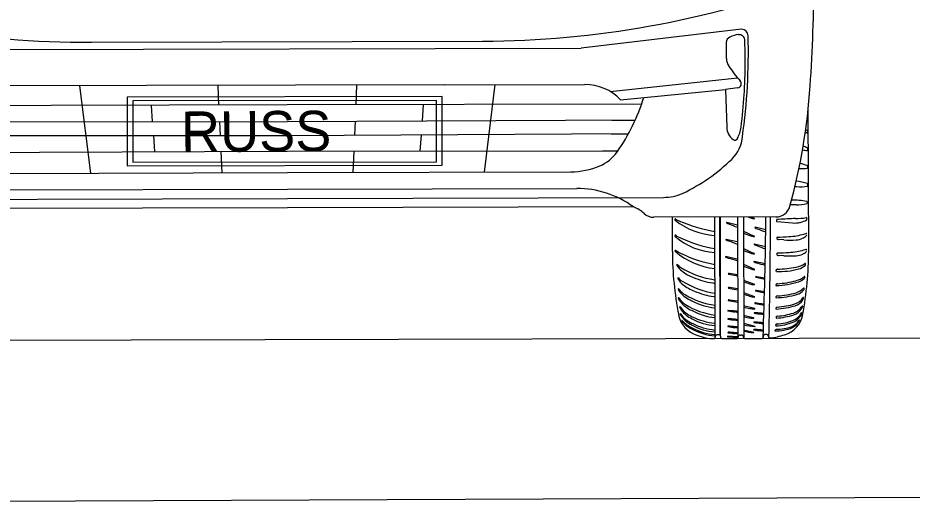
# Model space of a CAD drawing. Extents: x 10133 to 81668, y 4692 to 11018.
# Drawn here: x 28940.3 to 29064.3, y 5964.8 to 6032.5 of the extents above; entities that cross this region are included whole.
import ezdxf

# ---------------------------------------------------------------- set-up
doc = ezdxf.new("R2010")
doc.units = 0
for name, color, linetype in [('Cell', 7, 'Continuous'), ('Level 7', 7, 'Continuous'), ('PavementRemovalStage1', 7, 'Continuous'), ('SheetBorder', 7, 'Continuous')]:
    doc.layers.add(name, color=color, linetype=linetype)

msp = doc.modelspace()

# ---------------------------------------------------------------- linework, layer by layer
at = {"layer": 'Cell'}
for p, q in [((29040.67, 6030.95), (29018.43, 6028.34)), ((28950.5, 6029.14), (29004.76, 6029.28)), ((28936.84, 6028.13), (29018.43, 6028.34)), ((29022.47, 6022.31), (29040.1, 6024.21)), ((28999.45, 6023.24), (28936.34, 6023.08)), ((28948.84, 6023.11), (28950.37, 6010.99)), ((28968.02, 6023.16), (28968.15, 6020.42)), ((28987.27, 6023.21), (28987.16, 6020.47)), ((28999.45, 6023.24), (29018.95, 6023.29)), ((29006.45, 6023.26), (29004.99, 6011.14)), ((29040.13, 6022.84), (29038.46, 6022.58)), ((28958.77, 6020.39), (28958.95, 6018.13)), ((28996.53, 6020.49), (28996.37, 6018.23)), ((29049.98, 6000.18), (29049.93, 6020)), ((28968.26, 6018.14), (28968.35, 6016.2)), ((28987.06, 6018.19), (28986.98, 6016.25)), ((29022.7, 6018.33), (29025.92, 6018.34)), ((28996.23, 6016.3), (28996.07, 6014.05)), ((29022.61, 6016.42), (29024.97, 6016.43)), ((29049.74, 6016.58), (29049.74, 6016.58)), ((29049.8, 6016.83), (29049.79, 6016.64)), ((28959.1, 6016.21), (28959.27, 6013.96)), ((28968.45, 6013.99), (28968.59, 6011.04)), ((28986.89, 6014.03), (28986.76, 6011.09)), ((29021.37, 6014.1), (29023.55, 6014.11)), ((29049.8, 6014.42), (29049.8, 6014.18)), ((29049.81, 6011.96), (29049.8, 6011.72)), ((29049.83, 6009.48), (29049.84, 6009.24)), ((29049.76, 6007.01), (29049.76, 6006.83)), ((28977.69, 6006.19), (28929.71, 6006.06)), ((29025.67, 6006.31), (28977.69, 6006.19)), ((29045.45, 6004.91), (29028.51, 6004.87)), ((29031.06, 6004.88), (29031.07, 6000.13)), ((29031.42, 6004.55), (29031.42, 6004.55)), ((29031.46, 6004.45), (29031.46, 6004.45)), ((29036.94, 6004.89), (29036.98, 5988.11)), ((29040.09, 6003.78), (29038.64, 6004.15)), ((29040.09, 6004.9), (29040.14, 5988.16)), ((29040.92, 6004.9), (29040.97, 5988.16)), ((29042.07, 6004.9), (29042.43, 6004.74)), ((29045.52, 6004.49), (29045.53, 6004.36)), ((29045.53, 6004.36), (29045.53, 6004.3)), ((29045.55, 6004.28), (29047.72, 6004.08)), ((29049.74, 6004.57), (29049.75, 6004.74)), ((29040.93, 6002.96), (29042.44, 6002.26)), ((29044.02, 6003.12), (29042.57, 6003.49)), ((29031.43, 6002.29), (29031.43, 6002.29)), ((29031.47, 6002.2), (29031.47, 6002.2)), ((29040.06, 6001.45), (29038.55, 6001.79)), ((29045.6, 6001.83), (29045.6, 6001.83)), ((29045.64, 6002.13), (29045.64, 6002.13)), ((29046.53, 6001.73), (29045.8, 6001.77)), ((29049.32, 6002.55), (29049.61, 6002.64)), ((29031.44, 6000.27), (29031.44, 6000.27)), ((29031.47, 6000.17), (29031.47, 6000.17)), ((29031.54, 6000.26), (29031.54, 6000.26)), ((29040.94, 6000.55), (29042.44, 5999.85)), ((29043.99, 6000.78), (29042.48, 6001.13)), ((29049.32, 6000.35), (29049.62, 6000.43)), ((29040.02, 5999.06), (29038.5, 5999.41)), ((29045.6, 5999.63), (29045.6, 5999.63)), ((29045.64, 5999.93), (29045.64, 5999.93)), ((29046.54, 5999.53), (29045.81, 5999.57)), ((29040.94, 5998.36), (29042.45, 5997.67)), ((29043.95, 5998.4), (29042.43, 5998.75)), ((29049.56, 5998.31), (29049.56, 5998.39)), ((29038.86, 5997), (29039.92, 5996.78)), ((29040.11, 5996.89), (29039.01, 5997.07)), ((29042.66, 5996.56), (29043.71, 5996.33)), ((29043.91, 5996.44), (29042.81, 5996.62)), ((29049.47, 5996.53), (29049.47, 5996.61)), ((29040.95, 5996.17), (29042.47, 5995.6)), ((29032.13, 5994.48), (29032.13, 5994.48)), ((29040.12, 5994.94), (29039.02, 5995.12)), ((29040.95, 5994.45), (29042.47, 5993.88)), ((29042.61, 5994.65), (29043.67, 5994.42)), ((29043.86, 5994.53), (29042.76, 5994.71)), ((29049.37, 5994.91), (29049.37, 5994.99)), ((29032.13, 5993.23), (29032.13, 5993.23)), ((29040.13, 5993.24), (29039, 5993.39)), ((29042.54, 5992.91), (29043.62, 5992.72)), ((29043.82, 5992.83), (29042.69, 5992.98)), ((29049.28, 5993.59), (29049.28, 5993.67)), ((29032.32, 5992.01), (29032.32, 5992.01)), ((29036.97, 5992.31), (29036.97, 5992.31)), ((29040.96, 5992.65), (29042.5, 5992.26)), ((29049.16, 5992.5), (29049.16, 5992.5)), ((29036.97, 5990.95), (29036.97, 5990.95)), ((29040.13, 5990.64), (29040.13, 5990.64)), ((29040.96, 5991.31), (29042.35, 5990.96)), ((29043.77, 5991.45), (29043.77, 5991.45)), ((29036.98, 5989.85), (29036.98, 5989.85)), ((29040.13, 5989.64), (29040.13, 5989.64)), ((29040.96, 5990.18), (29042.51, 5989.79)), ((29040.96, 5989.97), (29040.96, 5989.97)), ((29040.96, 5989.26), (29042.36, 5988.95)), ((29043.69, 5989.19), (29043.69, 5989.19)), ((29043.73, 5990.18), (29043.73, 5990.18)), ((29036.98, 5988.97), (29036.98, 5988.97)), ((29036.98, 5988.41), (29036.98, 5988.41)), ((29036.98, 5988.11), (29036.98, 5988.11)), ((29037.72, 5988.47), (29037.72, 5988.47)), ((29037.95, 5988.04), (29040.04, 5988.05)), ((29040.14, 5988.31), (29038.74, 5988.37)), ((29040.13, 5988.81), (29040.13, 5988.81)), ((29040.23, 5988.42), (29040.23, 5988.42)), ((29040.87, 5988.43), (29040.87, 5988.43)), ((29041.06, 5988.05), (29043.48, 5988.06)), ((29044.31, 5988.5), (29044.47, 5988.21))]:
    msp.add_line(p, q, dxfattribs=at)
for points in [[(29023.86, 6021.17), (29038.46, 6022.58), (29038.62, 6017.35)], [(29026.81, 6020.57), (28977.65, 6020.44), (28928.5, 6020.31)], [(28929.39, 6018.11), (28977.66, 6018.14), (29025.93, 6018.36)], [(28930.34, 6016.22), (28977.67, 6016.2), (29024.99, 6016.47)], [(28931.8, 6013.86), (28977.67, 6014.02), (29023.54, 6014.1)], [(28938.4, 6010.96), (28977.68, 6011.06), (29016.96, 6011.17)], [(28937.55, 6008.66), (28977.68, 6008.76), (29017.82, 6008.87)], [(28925.53, 6007.35), (28977.69, 6007.48), (29029.84, 6007.62)], [(29037.7, 6004.89), (29037.72, 5988.47), (29037.68, 6004.89)], [(29038.86, 5995.06), (29040.12, 5994.79), (29040.12, 5994.79)], [(29038.85, 5993.32), (29040.12, 5993.11), (29040.12, 5993.11)], [(29049.06, 5991.58), (29049.06, 5991.58), (29049.06, 5991.58)], [(29032.15, 5991.45), (29032.15, 5991.45), (29032.15, 5991.45)], [(29032.4, 5990.5), (29032.4, 5990.5), (29032.4, 5990.5)], [(29048.73, 5990.58), (29048.73, 5990.58), (29048.73, 5990.58)], [(29040.49, 5988.54), (29040.55, 5988.54), (29040.61, 5988.54)]]:
    msp.add_lwpolyline(points, dxfattribs=at)
for centre, radius, start, end in [((29004.45, 6161.12), 131.84, 270.1364, 290.4198), ((28805.02, 6039.2), 245.7, 356.24, 359.743), ((28950.13, 6160.97), 131.84, 249.8789, 270.1623), ((29040.55, 6026.75), 3.46, 95.0278, 115.8532), ((29040.32, 6029.41), 0.781, 48.1066, 95.0278), ((29040.66, 6030.02), 0.926, 1.4761, 89.2056), ((28957, 6027.86), 84.62, 351.989, 1.4761), ((29040.23, 6029.31), 0.916, 0.9029, 48.1066), ((29065.15, 6027.93), 26.62, 177.438, 182.2816), ((29039.42, 6029.08), 0.865, 115.8532, 177.438), ((28870.61, 6026.64), 170.55, 359.4284, 0.9029), ((29040.58, 6026.95), 2.02, 182.2816, 213.3914), ((29052.94, 6035.1), 16.83, 213.3914, 222.2841), ((29040.07, 6023.4), 0.561, 276.1937, 42.2841), ((28990.62, 6025.44), 50.54, 355.9682, 359.4284), ((29018.97, 6016.57), 6.72, 43.1959, 90.1494), ((28966.14, 6028.65), 84.23, 344.6769, 356.2107), ((29000.81, 6029.63), 27.53, 325.2111, 342.7817), ((28950.17, 6028.29), 91.09, 353.1221, 355.9682), ((29040.83, 6017.42), 2.21, 181.777, 233.8972), ((29036.07, 6017.93), 4.56, 331.6652, 353.1221), ((29056.62, 6052.27), 36.34, 258.7187, 259.085), ((29046.26, 6010.54), 7.25, 61.1221, 62.8618), ((29049.73, 6016.64), 0.057, 278.0232, 359.1767), ((29049.73, 6016.83), 0.0661, 355.4519, 62.6226), ((29036.06, 6016.35), 4.73, 314.095, 356.6742), ((29039.75, 6015.95), 0.385, 233.8972, 331.6652), ((29018.9, 6017.07), 5.5, 292.8195, 325.2111), ((29104.42, 6402.59), 392.3, 261.8984, 261.9897), ((29046.41, 6008.1), 7.22, 62.234, 67.0932), ((29049.74, 6014.18), 0.057, 278.0232, 359.1767), ((29049.76, 6014.44), 0.0478, 339.8208, 68.9954), ((29021.33, 6031.55), 25.9, 295.5428, 314.095), ((29016.93, 6021.75), 10.58, 270.1494, 292.8195), ((29049.02, 6016.84), 5.23, 265.7538, 278.0232), ((29047.39, 6005.8), 6.67, 68.9954, 77.9807), ((29049.75, 6011.72), 0.057, 278.0232, 359.1767), ((29049.76, 6011.98), 0.0478, 339.8208, 68.9954), ((29017.85, 5995.64), 13.23, 53.7732, 90.1494), ((29051, 6034.69), 25.7, 263.4985, 264.005), ((29047.66, 6003.22), 6.67, 71.2848, 84.9331), ((29048.86, 6014.32), 5.23, 264.005, 280.3125), ((29049.78, 6009.24), 0.057, 280.3125, 1.4661), ((29049.79, 6009.49), 0.0478, 342.1101, 71.2848), ((29029.83, 6014.29), 6.66, 270.1494, 293.6418), ((29045.44, 6006.93), 2.01, 270.1494, 344.6769), ((29049.25, 6032.3), 25.7, 265.9972, 267.7547), ((29047.64, 5995.13), 12.12, 80.1903, 90.125), ((29048.45, 6011.84), 5.23, 267.7547, 284.0623), ((29049.7, 6007.01), 0.0628, 4.4153, 85.4549), ((29049.7, 6006.82), 0.057, 284.0623, 5.2159), ((29023.86, 6001.74), 4.92, 47.9118, 68.3799), ((29028.5, 6006.88), 2.01, 227.9118, 270.1494), ((29031.61, 6004.53), 0.193, 155.5287, 173.3854), ((29031.57, 6004.56), 0.148, 182.8931, 223.8732), ((29031.49, 6004.58), 0.0595, 53.6225, 155.5287), ((29037.77, 6012.64), 10.34, 232.3658, 265.4018), ((29032.62, 6006.11), 1.84, 233.6225, 250.4171), ((29040.98, 6025.63), 23.08, 247.0881, 259.9167), ((29038.7, 6020.06), 15.28, 263.3121, 263.3773), ((29038.63, 6004.11), 0.0401, 74.8147, 241.3176), ((29039.51, 6005.63), 1.79, 239.9232, 250.588), ((29059, 6056.13), 55.92, 248.9509, 250.2352), ((29060.06, 6057.69), 55.92, 250.7428, 251.1108), ((29043.09, 6008.09), 3.5, 251.1108, 258.7441), ((29042.41, 6004.7), 0.0401, 258.7441, 65.2469), ((28342.5, 6012.98), 701.6, 357.98088, 359.34098), ((27960.4, 6011.82), 1084.33, 358.75258, 359.63505), ((29045.57, 6004.5), 0.0456, 95.8878, 189.5919), ((29045.56, 6004.3), 0.0264, 180.963, 260.1571), ((29046.86, 5992.03), 12.58, 94.7626, 95.8878), ((29048.84, 5968.26), 36.43, 91.0525, 94.7626), ((29048.02, 6007.41), 3.34, 264.8801, 284.3551), ((29047.97, 6015.54), 10.85, 271.0525, 278.8398), ((29047.83, 6008.14), 4.1, 284.3551, 297.3289), ((29049.65, 6004.73), 0.0931, 8.1851, 102.06), ((29049.66, 6004.57), 0.0805, 308.0519, 359.5953), ((29060.06, 6055.21), 55.92, 249.9903, 251.1108), ((29042.56, 6003.45), 0.0401, 74.8147, 241.3176), ((29043.44, 6004.96), 1.79, 239.9232, 250.588), ((29062.93, 6055.46), 55.92, 248.9509, 250.2352), ((29031.77, 6002.24), 0.345, 161.0845, 171.0107), ((29031.53, 6002.27), 0.0984, 167.7589, 229.1775), ((29031.5, 6002.33), 0.0595, 53.5854, 161.0845), ((29037.54, 6009.39), 9.42, 229.8019, 266.3853), ((29033.43, 6004.94), 3.18, 233.5854, 248.9357), ((29039.74, 6017.97), 17.65, 245.021, 260.9088), ((29038.54, 6001.76), 0.0401, 74.8147, 241.3176), ((29039.38, 6003.75), 2.2, 246.8187, 256.4349), ((29058.95, 6053.79), 55.92, 248.9509, 250.2547), ((29043.09, 6005.62), 3.5, 251.1108, 258.7441), ((29042.42, 6002.23), 0.0401, 258.7441, 65.2469), ((29045.77, 6001.96), 0.213, 126.7257, 217.0458), ((29045.9, 6002.5), 0.736, 245.805, 262.6722), ((29045.63, 6025.43), 23.3, 270.0328, 273.9989), ((29047.39, 6017.11), 15.41, 266.8145, 273.1056), ((29046.48, 6013.19), 11.03, 273.9989, 279.5766), ((29048.09, 6004.22), 2.5, 273.1056, 294.9917), ((29046.97, 6010.31), 8.11, 279.5766, 286.8307), ((29048.37, 6003.62), 1.83, 294.9917, 313.49), ((29049.62, 6002.54), 0.0975, 19.7919, 91.5886), ((29049.47, 6002.46), 0.234, 313.49, 352.1257), ((29031.49, 6000.18), 0.0982, 54.5176, 120.1002), ((29031.53, 6000.25), 0.0984, 167.7589, 229.1775), ((29037.9, 6007.38), 9.66, 228.2768, 264.3964), ((29035.71, 6006.97), 7.9, 238.1728, 244.3482), ((29060.07, 6052.81), 55.92, 249.9903, 251.1108), ((29042.46, 6001.09), 0.0401, 74.8147, 241.3176), ((29043.31, 6003.08), 2.2, 246.8187, 256.4349), ((29062.88, 6053.13), 55.92, 248.9509, 250.2547), ((29046.97, 6008.11), 8.11, 279.5766, 286.8307), ((29002.15, 6000.26), 47.83, 349.2873, 359.9085), ((29049.62, 6000.34), 0.0975, 19.7919, 91.5886), ((29049.48, 6000.26), 0.234, 313.49, 352.1257), ((29078.9, 6000.46), 47.83, 180.3902, 191.0114), ((29040.16, 6015.91), 17.88, 243.885, 259.6679), ((29038.49, 5999.37), 0.0401, 74.8147, 241.3176), ((29039.34, 6001.36), 2.2, 246.8187, 256.4349), ((29045.18, 6020.21), 21.93, 253.1625, 256.3983), ((29043.1, 6003.21), 3.5, 251.1108, 258.7441), ((29042.42, 5999.82), 0.0401, 258.7441, 65.2469), ((29045.77, 5999.76), 0.213, 126.7257, 217.0458), ((29045.9, 6000.3), 0.736, 245.805, 262.6722), ((29045.63, 6023.23), 23.3, 270.0328, 273.9989), ((29047.4, 6014.91), 15.41, 266.8145, 273.1056), ((29046.49, 6010.99), 11.03, 273.9989, 279.5766), ((29048.1, 6002.02), 2.5, 273.1056, 294.9917), ((29048.38, 6001.42), 1.83, 294.9917, 313.49), ((29031.72, 5998.3), 0.0462, 37.6653, 179.6144), ((29031.92, 5998.3), 0.245, 179.6144, 214.0788), ((29034.64, 6000.14), 3.53, 214.0788, 230.3744), ((29032.99, 5999.28), 1.55, 217.6653, 242.0414), ((29038.64, 6008.21), 12.12, 238.2361, 262.0442), ((29060.08, 6050.62), 55.92, 249.9903, 251.1108), ((29043.1, 6001.02), 3.5, 251.1108, 258.7441), ((29042.42, 5998.71), 0.0401, 74.8147, 241.3176), ((29043.27, 6000.7), 2.2, 246.8187, 256.4349), ((29049.11, 6019.55), 21.93, 253.1625, 256.3983), ((29046.01, 6007.36), 10, 267.0461, 284.966), ((29043.71, 6025.65), 28.06, 273.9252, 279.3141), ((29047.76, 6000.96), 3.04, 279.3141, 304.1699), ((29047.99, 5999.95), 2.32, 284.966, 310.222), ((29049.5, 5998.39), 0.0595, 357.3482, 124.1699), ((29049.36, 5998.32), 0.195, 310.222, 356.6448), ((29031.87, 5996.42), 0.0462, 37.6653, 179.6144), ((29033.14, 5997.4), 1.55, 217.6653, 242.0414), ((29035.64, 6001.35), 5.09, 230.3744, 251.082), ((29038.19, 6006.15), 10.5, 246.3934, 261.7054), ((29038.87, 5997.04), 0.0377, 85.4711, 257.2654), ((29038.72, 5993.57), 3.51, 85.2586, 87.5363), ((29040.19, 5998), 1.25, 257.6183, 266.5384), ((29042.43, 5997.63), 0.0401, 258.7441, 65.2469), ((29042.66, 5996.59), 0.0377, 85.4711, 257.2654), ((29042.52, 5993.13), 3.51, 85.2586, 87.5363), ((29045.65, 5997.43), 0.225, 93.9252, 163.2043), ((29045.52, 5997.47), 0.0933, 163.2043, 252.0951), ((29047.55, 5998.82), 2.83, 284.4815, 310.2791), ((29049.11, 5996.64), 0.37, 312.7664, 342.8809), ((29049.41, 5996.61), 0.0595, 357.3482, 124.1699), ((29032.07, 5996.42), 0.245, 179.6144, 214.0788), ((29034.79, 5998.26), 3.53, 214.0788, 230.3744), ((29038.77, 6006.25), 12.04, 238.126, 261.3972), ((29035.79, 5999.46), 5.09, 230.3744, 251.082), ((29038.53, 6011.82), 16.17, 263.4158, 264.4387), ((29060.08, 6048.49), 55.92, 249.9903, 250.9016), ((29042.52, 5997.76), 2.23, 250.9006, 268.1038), ((29042.45, 5995.56), 0.0401, 258.7441, 65.2469), ((29043.98, 5997.56), 1.25, 257.6183, 266.5384), ((29045.53, 5995.47), 0.0933, 163.2043, 252.0951), ((29045.65, 5995.44), 0.225, 93.9252, 163.2043), ((29044.75, 6009.02), 13.65, 273.158, 286.3733), ((29044.99, 6008.04), 12.4, 272.9903, 285.2808), ((29047.09, 5999.37), 3.76, 293.5176, 307.127), ((29031.94, 5994.89), 0.0462, 37.6653, 179.6144), ((29033.45, 5995.51), 1.68, 201.681, 217.9233), ((29034.22, 5996.49), 2.73, 215.0249, 240.6989), ((29035.35, 5997.22), 4.22, 220.298, 248.362), ((29038.44, 6003.34), 10.77, 238.9469, 262.1794), ((29038.34, 6004.26), 10.5, 246.3934, 261.7054), ((29038.87, 5995.09), 0.0377, 85.4711, 257.2654), ((29038.73, 5991.63), 3.51, 85.2586, 87.5363), ((29060.09, 6046.77), 55.92, 249.9903, 250.9016), ((29042.62, 5994.68), 0.0377, 85.4711, 257.2654), ((29042.47, 5991.22), 3.51, 85.2586, 87.5363), ((29043.94, 5995.65), 1.25, 257.6183, 266.5384), ((29045.66, 5993.75), 0.225, 93.9252, 163.2043), ((29044.75, 6007.33), 13.65, 273.158, 285.2807), ((29044.99, 6006.35), 12.4, 272.9903, 285.2808), ((29047.42, 5996.84), 2.58, 288.9483, 315.925), ((29047.68, 5996.22), 2.16, 288.0308, 317.2478), ((29049.01, 5995.02), 0.37, 312.7664, 342.8809), ((29049.31, 5994.99), 0.0595, 357.3482, 124.1699), ((29031.94, 5993.64), 0.0462, 37.6653, 179.6144), ((29033.45, 5994.26), 1.68, 201.681, 217.9233), ((29034.59, 5995.34), 3.1, 212.4567, 236.5311), ((29035.67, 5996.05), 4.52, 218.484, 245.6084), ((29038.44, 6001.98), 10.77, 238.9469, 262.1794), ((29037.79, 6000.63), 8.36, 241.4304, 264.3542), ((29038.68, 6009.94), 16.17, 263.4158, 263.9218), ((29038.86, 5993.36), 0.0377, 85.4711, 257.2654), ((29038.71, 5989.9), 3.51, 85.2586, 87.5363), ((29042.52, 5996.04), 2.23, 250.9006, 268.1038), ((29042.45, 5993.84), 0.0401, 258.7441, 65.2469), ((29042.55, 5992.95), 0.0377, 85.4711, 257.2654), ((29042.4, 5989.49), 3.51, 85.2586, 87.5363), ((29043.89, 5993.95), 1.25, 257.6183, 266.5384), ((29045.53, 5993.79), 0.0933, 163.2043, 252.0951), ((29044.68, 6004.88), 12.5, 274.424, 285.752), ((29047.28, 5995.03), 2.32, 290.118, 325.5234), ((29047.46, 5994.57), 2.07, 289.0749, 325.7997), ((29048.64, 5993.83), 0.684, 321.8805, 339.4113), ((29049.22, 5993.67), 0.0595, 357.3482, 124.1699), ((29032.13, 5992.42), 0.0462, 37.6653, 179.6144), ((29033.64, 5993.04), 1.68, 201.681, 217.9233), ((29032.18, 5991.46), 0.0345, 41.9847, 208.1679), ((29035.29, 5994.55), 3.77, 213.9124, 247.0376), ((29035.41, 5993.73), 3.91, 215.0753, 246.0911), ((29035.33, 5994.19), 3.72, 215.8267, 245.753), ((29037.8, 5999.27), 8.36, 241.4304, 264.3542), ((29038.8, 5991.9), 0.0287, 90.9709, 265.2839), ((29038.13, 5975.39), 16.55, 84.2063, 87.6746), ((29049.4, 6067.8), 76.66, 262.0489, 262.7911), ((29039.56, 5990.66), 1.11, 59.033, 78.2953), ((29039.56, 5989.6), 2.27, 75.5483, 83.9597), ((29054.2, 6046.76), 55.92, 256.3006, 257.2119), ((29042.32, 5994.41), 2.23, 257.2109, 274.4141), ((29042.43, 5991.6), 0.0287, 90.9709, 265.2839), ((29041.76, 5975.09), 16.55, 84.2063, 87.6746), ((29053.03, 6067.49), 76.66, 262.0489, 262.7911), ((29042.49, 5992.22), 0.0401, 265.0544, 71.5572), ((29043.42, 5990.86), 0.694, 59.1617, 89.1784), ((29045.53, 5992.23), 0.0933, 163.2043, 252.0951), ((29045.66, 5992.2), 0.225, 93.9252, 163.2043), ((29044.43, 6005.86), 13.76, 274.4777, 285.6374), ((29044.76, 6001.72), 10.6, 274.8021, 287.1016), ((29046.74, 5992.94), 2.61, 293.4829, 329.1108), ((29046.96, 5992.4), 2.25, 292.9443, 338.6046), ((29046.83, 5994.11), 2.73, 292.6629, 325.2549), ((29047.2, 5993.34), 2.13, 290.4575, 326.6417), ((29049.01, 5991.58), 0.0463, 6.982, 148.3285), ((29048.5, 5992.65), 0.679, 314.5045, 346.6929), ((29049.1, 5992.5), 0.0595, 357.3482, 124.1699), ((29035.51, 5992.02), 3.63, 191.0114, 253.4078), ((29035.29, 5993.17), 3.57, 208.7215, 245.5033), ((29032.43, 5990.52), 0.0345, 41.9847, 208.1679), ((29035.38, 5992.78), 3.76, 217.4509, 243.9446), ((29035.84, 5993.72), 4.65, 223.21, 244.5013), ((29037.51, 5997.44), 7.6, 240.8513, 266.0143), ((29038.05, 5999.84), 9.73, 244.2088, 263.647), ((29038.78, 5990.76), 0.0287, 90.9709, 265.2839), ((29038.11, 5974.26), 16.55, 84.2063, 87.6746), ((29049.39, 6066.66), 76.66, 262.0489, 262.7911), ((29039.65, 5989.64), 0.975, 60.6195, 83.1706), ((29039.64, 5989.39), 1.34, 68.496, 83.7657), ((29054.04, 6045.47), 55.92, 256.4694, 257.2119), ((29042.16, 5993.11), 2.23, 257.2109, 274.4141), ((29042.34, 5990.93), 0.0401, 265.0544, 71.5572), ((29042.39, 5990.32), 0.0287, 90.9709, 265.2839), ((29041.71, 5973.81), 16.55, 84.2063, 87.6746), ((29052.99, 6066.21), 76.66, 262.0489, 262.7911), ((29043.37, 5989.58), 0.694, 59.1617, 89.1784), ((29043.19, 5990.35), 1.11, 58.3071, 78.2953), ((29045.54, 5990.97), 0.0933, 163.2043, 252.0951), ((29045.66, 5990.93), 0.225, 93.9252, 163.2043), ((29045.01, 5997.55), 7.76, 273.2473, 291.3734), ((29044.51, 6002.66), 11.83, 274.8281, 286.8648), ((29045.11, 5997.71), 7.65, 273.6109, 290.4043), ((29045.59, 5992.04), 3.63, 286.891, 349.2873), ((29046.69, 5991.87), 2.36, 294.9721, 327.6041), ((29046.72, 5991.58), 2.24, 296.6949, 333.5193), ((29048.7, 5990.58), 0.0301, 351.758, 136.433), ((29037.69, 5996.51), 8.13, 240.8614, 265.0016), ((29037.51, 5996.55), 7.6, 240.8513, 266.0143), ((29038.06, 5998.69), 9.52, 243.5921, 263.5032), ((29037.63, 5996.75), 8.16, 242.3134, 265.4083), ((29038.79, 5989.73), 0.0287, 90.9709, 265.2839), ((29038.11, 5973.23), 16.55, 84.2063, 87.6746), ((29049.39, 6065.63), 76.66, 262.0489, 262.7911), ((29039.48, 5986.47), 3.11, 77.9784, 84.7725), ((29036.4, 5965.97), 23.96, 81.0493, 81.8908), ((29043.97, 6003.42), 13.79, 257.4115, 263.8679), ((29043.39, 6000.6), 11.77, 258.1066, 264.9403), ((29042.35, 5989.29), 0.0287, 90.9709, 265.2839), ((29041.68, 5972.78), 16.55, 84.2063, 87.6746), ((29052.95, 6065.18), 76.66, 262.0489, 262.7911), ((29042.5, 5989.75), 0.0401, 265.0544, 71.5572), ((29042.52, 5984.18), 5.01, 76.5484, 80.7403), ((29039.97, 5965.52), 23.96, 81.0493, 81.8908), ((29043.14, 5989.07), 1.11, 58.3071, 78.2953), ((29045.34, 5989.17), 0.0609, 163.239, 266.2874), ((29045.49, 5989.1), 0.225, 93.9252, 158.4475), ((29045.4, 5995.15), 6.04, 269.4189, 292.6689), ((29045.61, 5989.86), 0.225, 93.9252, 163.2043), ((29045.48, 5989.9), 0.0933, 163.2043, 252.0951), ((29045.41, 5995.97), 6.64, 270.6076, 290.02), ((29036.89, 5994.1), 6.06, 246.4888, 269.9434), ((29036.88, 5988.14), 0.104, 270.0599, 339.5281), ((29037.79, 5988.11), 0.807, 152.5154, 180.1315), ((29037.39, 5988.01), 0.573, 54.6603, 123.8884), ((29043.53, 5989.25), 5.86, 187.6, 190.2435), ((29037.96, 5988.24), 0.198, 189.8693, 265.3999), ((29038.74, 5988.34), 0.0337, 85.9557, 268.7798), ((29074.17, 6465.87), 478.88, 265.7571, 265.9249), ((29038.79, 5988.9), 0.0287, 90.9709, 265.2839), ((29049.39, 6064.79), 76.66, 262.0489, 262.7911), ((29038.12, 5972.39), 16.55, 84.2063, 87.6746), ((29038.88, 5978.82), 9.96, 82.767, 84.8786), ((29039.3, 5983.14), 5.73, 81.6027, 85.1056), ((29040.02, 5988.16), 0.116, 280.8479, 358.4396), ((29040.6, 5988.15), 0.462, 142.8823, 178.4396), ((29040.48, 5988.21), 0.334, 89.2929, 139.884), ((29040.62, 5988.21), 0.334, 40.4148, 91.0059), ((29040.51, 5988.15), 0.462, 1.8591, 37.4164), ((29041.08, 5988.16), 0.116, 181.8591, 259.4509), ((29042.35, 5988.92), 0.0342, 275.1846, 63.3064), ((29043.46, 5988.25), 0.198, 274.8989, 1.7289), ((29044.09, 5988.26), 0.434, 155.4338, 179.7962), ((29043.93, 5988.33), 0.257, 118.9476, 155.4338), ((29044.16, 5987.93), 0.718, 101.8018, 118.9476), ((29044.07, 5988.36), 0.277, 30.1471, 101.8018), ((29044.63, 5988.3), 0.179, 210.1471, 276.1352), ((29043.48, 5997.95), 9.89, 276.7699, 288.6302)]:
    msp.add_arc(centre, radius, start, end, dxfattribs=at)
at = {"layer": 'Level 7'}
msp.add_line((28779.45, 5964.82), (29752.89, 5969), dxfattribs=at)
at = {"layer": 'PavementRemovalStage1'}
msp.add_line((29752.89, 5989.91), (28720.67, 5987.21), dxfattribs=at)
at = {"layer": 'SheetBorder'}
for points in [[(28999.15, 6021.6), (28955.47, 6021.52), (28955.48, 6012.01), (28999.16, 6012.1)], [(28998.37, 6021.08), (28956.24, 6021), (28956.26, 6012.49), (28998.38, 6012.56)]]:
    msp.add_lwpolyline(points, close=True, dxfattribs=at)

# ---------------------------------------------------------------- texts
msp.add_text('RUSS', height=5.612, rotation=0.331, dxfattribs=at).set_placement((28962.94, 6013.92))

doc.saveas('drawing.dxf')
